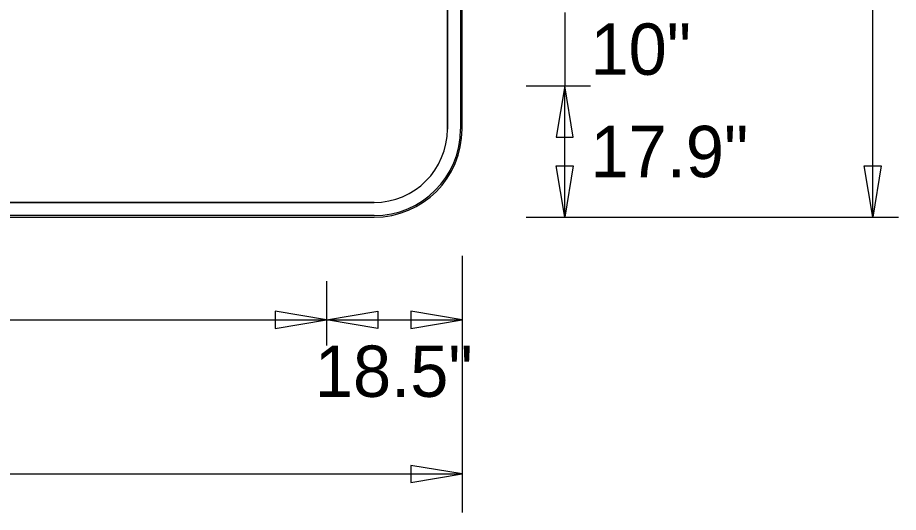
# Model space of a CAD drawing. Extents: x 2149961 to 2150220, y 145114 to 145240.
# Drawn here: x 2149993.88 to 2150003.89, y 145213.41 to 145219.03 of the extents above; entities that cross this region are included whole.
import ezdxf

# ---------------------------------------------------------------- set-up
doc = ezdxf.new("R2010")
doc.units = 0
for name, color, linetype in [('GSBWFILL', 7, 'Continuous'), ('GSCOLORFILL', 7, 'Continuous'), ('GSDIMS', 7, 'Continuous'), ('GSOUTLINE', 7, 'Continuous')]:
    doc.layers.add(name, color=color, linetype=linetype)

msp = doc.modelspace()

# ---------------------------------------------------------------- linework, layer by layer
at = {"layer": 'GSBWFILL'}
for p, q in [((2149998.763, 145232.262), (2149998.763, 145217.762)), ((2149998.93, 145217.762), (2149998.93, 145232.262)), ((2149997.93, 145216.929), (2149984.431, 145216.929)), ((2149984.431, 145216.762), (2149997.93, 145216.762))]:
    msp.add_line(p, q, dxfattribs=at)
for radius in [1, 0.833]:
    msp.add_arc((2149997.93, 145217.762), radius, 270, 0, dxfattribs=at)
at = {"layer": 'GSCOLORFILL'}
for p, q in [((2149998.763, 145232.262), (2149998.763, 145217.762)), ((2149998.913, 145232.262), (2149998.913, 145217.762)), ((2149998.93, 145217.762), (2149998.93, 145232.262)), ((2149998.93, 145217.762), (2149998.93, 145232.262)), ((2149998.93, 145217.762), (2149998.93, 145232.262)), ((2149997.93, 145216.929), (2149984.431, 145216.929)), ((2149997.93, 145216.779), (2149984.43, 145216.779)), ((2149984.43, 145216.762), (2149997.93, 145216.762)), ((2149984.43, 145216.762), (2149997.93, 145216.762)), ((2149984.431, 145216.762), (2149997.93, 145216.762))]:
    msp.add_line(p, q, dxfattribs=at)
for radius in [1, 1, 0.833, 1, 0.983]:
    msp.add_arc((2149997.93, 145217.762), radius, 270, 0, dxfattribs=at)
at = {"layer": 'GSDIMS'}
for p, q in [((2150003.596, 145216.762), (2150003.596, 145227.27)), ((2150000.096, 145219.087), (2150000.096, 145218.254)), ((2149999.659, 145218.254), (2150000.388, 145218.254)), ((2149999.659, 145218.254), (2150000.388, 145218.254)), ((2150000.096, 145216.762), (2150000.096, 145218.254)), ((2149999.659, 145216.762), (2150000.388, 145216.762)), ((2149999.659, 145216.762), (2150003.159, 145216.762)), ((2150003.159, 145216.762), (2150003.888, 145216.762)), ((2149998.93, 145216.324), (2149998.93, 145213.408)), ((2149997.388, 145216.033), (2149997.388, 145215.303)), ((2149997.388, 145216.033), (2149997.388, 145215.303)), ((2149998.93, 145216.033), (2149998.93, 145215.303)), ((2149984.971, 145215.595), (2149997.388, 145215.595)), ((2149997.388, 145215.595), (2149998.93, 145215.595)), ((2149998.93, 145214.283), (2149998.93, 145213.553)), ((2149983.429, 145213.845), (2149998.93, 145213.845))]:
    msp.add_line(p, q, dxfattribs=at)
for points in [[(2150000.096, 145218.254), (2149999.999, 145217.67), (2150000.193, 145217.67)], [(2150000.096, 145216.762), (2149999.999, 145217.345), (2150000.193, 145217.345)], [(2150003.596, 145216.762), (2150003.499, 145217.345), (2150003.693, 145217.345)], [(2149997.388, 145215.595), (2149996.805, 145215.692), (2149996.805, 145215.498)], [(2149997.388, 145215.595), (2149997.971, 145215.692), (2149997.971, 145215.498)], [(2149998.93, 145215.595), (2149998.346, 145215.692), (2149998.346, 145215.498)], [(2149998.93, 145213.845), (2149998.346, 145213.942), (2149998.346, 145213.748)]]:
    msp.add_lwpolyline(points, close=True, dxfattribs=at)
at = {"layer": 'GSOUTLINE'}
for p, q in [((2149998.763, 145217.762), (2149998.763, 145232.262)), ((2149998.93, 145217.762), (2149998.93, 145232.262)), ((2149984.43, 145216.929), (2149997.93, 145216.929)), ((2149984.43, 145216.762), (2149997.93, 145216.762))]:
    msp.add_line(p, q, dxfattribs=at)
for radius in [1, 0.833]:
    msp.add_arc((2149997.93, 145217.762), radius, 270, 0, dxfattribs=at)

# ---------------------------------------------------------------- texts
at = {"layer": 'GSDIMS'}
for s, p in [('10"', (2150000.388, 145218.379)), ('17.9"', (2150000.388, 145217.216)), ('18.5"', (2149997.256, 145214.72))]:
    msp.add_text(s, height=0.5833, dxfattribs=at).set_placement(p)

doc.saveas('drawing.dxf')
